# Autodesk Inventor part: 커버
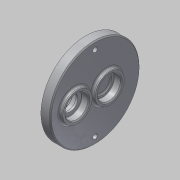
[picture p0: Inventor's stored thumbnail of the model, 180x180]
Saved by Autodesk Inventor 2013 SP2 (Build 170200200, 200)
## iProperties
Created: 2016-02
Part Number: 커버
Material: 알루미늄 6061
Document SubType Name: Modeling
Designer: mduedu
Density: 2.71 g/cm^3
Author: mduedu
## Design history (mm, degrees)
sketch "스케치1"
  geometry: C1 r 43 at (0, 0); 1 further point
  constraints: 1 centre point, 1 coincident
  dimensions: "d0" = 86 diameter of C1
extrude "돌출1" new body sketch "스케치1" distance "d1" = 9; taper "d2" = 0 deg
sketch "스케치2"
  geometry: C1 r 14 at (0, 11); 1 further point
  constraints: 1 centre point, 1 vertical alignment
  dimensions: "d3" = 28 diameter of C1; "d6" = 11 distance of C1.centre point (0, 0)
extrude "돌출2" join sketch "스케치2" distance "d7" = 3; taper "d8" = 0 deg
sketch "스케치3"
  geometry: C1 r 14 at (0, -20); 1 further point
  constraints: 1 centre point, 1 vertical alignment
  dimensions: "d9" = 28 diameter of C1; "d10" = 20 distance of C1.centre point (0, 0)
extrude "돌출3" join sketch "스케치3" distance "d11" = 3; taper "d12" = 0 deg
hole "구멍1" diameter "d15" = 22; stored, may be unused: countersink angle "d19" = 90 deg, drill point angle "d21" = 0 deg; dims "d13" = 10, "d14" = 10, "d16" = 6, "d17" = 4, "d18" = 2, "d20" = 7
hole "구멍2" diameter "d24" = 18; stored, may be unused: countersink angle "d28" = 90 deg, drill point angle "d30" = 0 deg; dims "d22" = 10, "d23" = 10, "d25" = 6, "d26" = 4, "d27" = 2, "d29" = 1
hole "구멍3" diameter "d33" = 22; stored, may be unused: countersink angle "d37" = 90 deg, drill point angle "d39" = 0 deg; dims "d34" = 6, "d35" = 4, "d36" = 2, "d38" = 7, "d73" = 10, "d74" = 10
sketch "스케치4"
  geometry: C1 r 14 at (0, -20) reference; C2 r 18 at (0, -20); 1 further point
  constraints: 1 centre point, 1 coincident
  dimensions: "d40" = 36 diameter of C2
extrude "돌출4" join sketch "스케치4" distance "d41" = 4; taper "d42" = 0 deg
hole "구멍4" diameter "d45" = 22; stored, may be unused: countersink angle "d49" = 90 deg, drill point angle "d51" = 0 deg; dims "d43" = 10, "d44" = 10, "d46" = 6, "d47" = 4, "d48" = 2, "d50" = 7
hole "구멍5" diameter "d54" = 15; stored, may be unused: countersink angle "d58" = 90 deg, drill point angle "d60" = 0 deg; dims "d52" = 10, "d53" = 10, "d55" = 6, "d56" = 4, "d57" = 2, "d59" = 7
fillet "모깎기1" dims "d61" = 0.3
fillet "모깎기2" dims "d62" = 2
chamfer "모따기1" distance "d63" = 1; stored, may be unused: second distance "d64" = 2, angle "d65" = 45 deg
fillet "모깎기6" dims "d88" = 2
sketch "스케치5" dims "d67" = 72
  geometry: 4 further points
  constraints: 2 horizontal alignment, 1 coincident, 5 other
  dimensions: "d71" = 360 deg dimension on point (0, 0) point (-36, 0) (derived)
fillet "모깎기4" dims "d75" = 2
sketch "스케치6"
  geometry: 2 further points
hole "구멍6" sketch "스케치6" at (36, 0), (-36, 0) diameter "d76" = 4.5; stored, may be unused: countersink angle "d80" = 90 deg, drill point angle "d82" = 0 deg; dims "d77" = 6, "d78" = 8, "d79" = 4.6, "d81" = 8
chamfer "모따기2" distance "d90" = 1; stored, may be unused: second distance "d91" = 2, angle "d92" = 45 deg
node "솔리드1"
